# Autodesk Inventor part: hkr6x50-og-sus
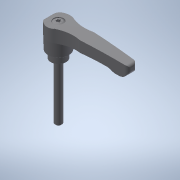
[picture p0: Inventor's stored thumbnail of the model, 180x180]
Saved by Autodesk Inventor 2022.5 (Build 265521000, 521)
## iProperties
Created: 2017-09
Part Number: hkr6x50-og-sus
Material: 一般
Document SubType Name: Modeling
Designer: imaocorp
Density: 1 g/cm^3
Appearance: 既定
Author: imaocorp
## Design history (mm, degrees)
node "hkr6x50-og-sus.x_t1"
node "hkr6x50-og-sus"
node "Base1"
